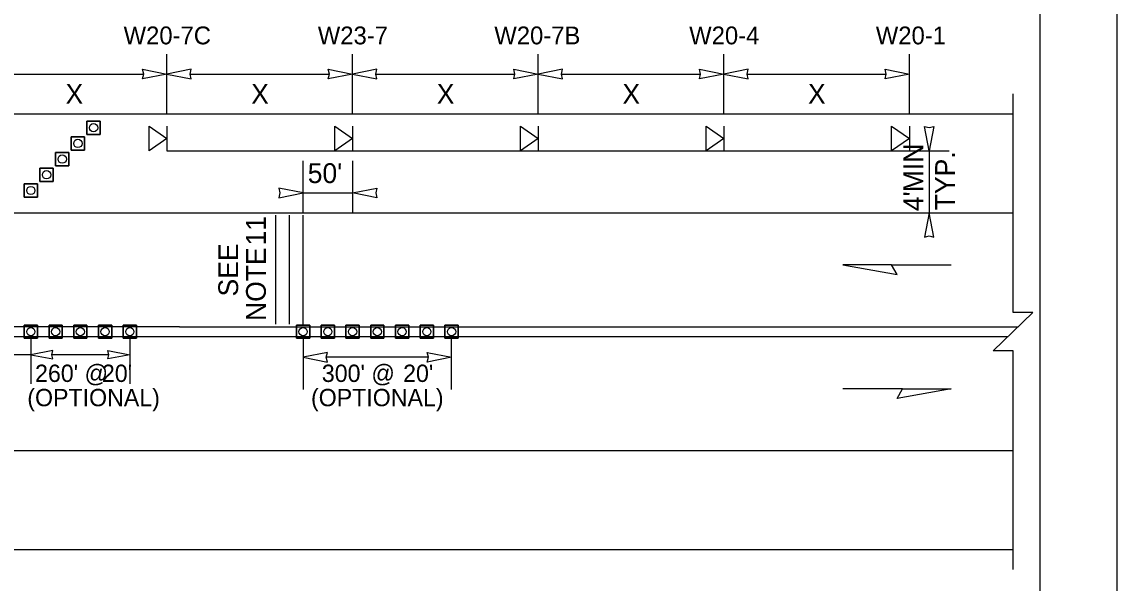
# Model space of a CAD drawing. Extents: x 99999.1 to 100095.7, y 99995 to 100010.7.
# Drawn here: x 100011.637 to 100016.062, y 100005.597 to 100007.863 of the extents above; entities that cross this region are included whole.
import ezdxf

# ---------------------------------------------------------------- set-up
doc = ezdxf.new("R2010")
doc.units = 0
for name, color, linetype in [('RD_ED_ShoulderPavedEdge', 7, 'Continuous'), ('RD_MK_LineDblYellowCenter', 7, 'Continuous'), ('RD_MK_LineEdgeWhite', 7, 'Continuous'), ('RD_MK_LineNoPass', 7, 'Continuous'), ('RD_MK_LineSkipCenter', 7, 'Continuous'), ('SH_GI_PlotLimits', 7, 'Continuous'), ('SH_GI_SheetBorder', 7, 'Continuous'), ('TR_SN_ConstructionSigns', 7, 'Continuous'), ('TR_WZ_PortableSignMountBlk-Org', 7, 'Continuous'), ('TR_WZ_TrafficCone', 7, 'Continuous'), ('TR_WZ_WorkZoneDetails', 7, 'Continuous'), ('TR_WZ_WorkZoneTextCurrent', 7, 'Continuous')]:
    doc.layers.add(name, color=color, linetype=linetype)

msp = doc.modelspace()

# ---------------------------------------------------------------- linework, layer by layer
at = {"layer": 'RD_ED_ShoulderPavedEdge'}
for p, q in [((100000.1076, 100007.4923), (100015.6424, 100007.4923)), ((100000.1076, 100005.7323), (100015.6424, 100005.7323))]:
    msp.add_line(p, q, dxfattribs=at)
at = {"layer": 'RD_MK_LineDblYellowCenter'}
for p, q in [((100012.2733, 100006.6323), (100015.6631, 100006.6323)), ((100012.2733, 100006.5923), (100015.6218, 100006.5923))]:
    msp.add_line(p, q, dxfattribs=at)
at = {"layer": 'RD_MK_LineEdgeWhite'}
for p, q in [((100000.1076, 100007.0923), (100015.6424, 100007.0923)), ((100000.1076, 100006.1323), (100015.6424, 100006.1323))]:
    msp.add_line(p, q, dxfattribs=at)
at = {"layer": 'RD_MK_LineNoPass'}
msp.add_line((100011.4733, 100006.5923), (100012.2733, 100006.5923), dxfattribs=at)
at = {"layer": 'RD_MK_LineSkipCenter'}
msp.add_lwpolyline([(100012.2733, 100006.6323), (100011.4733, 100006.6323)], dxfattribs=at)
at = {"layer": 'SH_GI_PlotLimits'}
msp.add_lwpolyline([(99999.0625, 99999.6875), (100016.0625, 99999.6875), (100016.0625, 100010.6875), (99999.0625, 100010.6875)], close=True, dxfattribs=at)
at = {"layer": 'SH_GI_SheetBorder'}
msp.add_line((100015.75, 100010.375), (100015.75, 100000), dxfattribs=at)
at = {"layer": 'TR_WZ_PortableSignMountBlk-Org'}
for p, q in [((100012.2233, 100007.4422), (100012.2233, 100007.3422)), ((100012.9733, 100007.4422), (100012.9733, 100007.3422)), ((100013.7233, 100007.4422), (100013.7233, 100007.3422)), ((100014.4733, 100007.4422), (100014.4733, 100007.3422)), ((100015.2233, 100007.4422), (100015.2233, 100007.3422))]:
    msp.add_line(p, q, dxfattribs=at)
for points in [[(100012.2233, 100007.3923), (100012.1515, 100007.3422), (100012.1515, 100007.4422)], [(100012.9733, 100007.3923), (100012.9015, 100007.3422), (100012.9015, 100007.4422)], [(100013.7233, 100007.3923), (100013.6515, 100007.3422), (100013.6515, 100007.4422)], [(100014.4733, 100007.3923), (100014.4015, 100007.3422), (100014.4015, 100007.4422)], [(100015.2233, 100007.3923), (100015.1515, 100007.3422), (100015.1515, 100007.4422)]]:
    msp.add_lwpolyline(points, close=True, dxfattribs=at)
at = {"layer": 'TR_WZ_TrafficCone'}
for points in [[(100011.9533, 100007.4623), (100011.9, 100007.4623), (100011.9, 100007.409), (100011.9533, 100007.409), (100011.9533, 100007.4623)], [(100011.9533, 100007.409), (100011.9, 100007.409), (100011.9, 100007.4623), (100011.9533, 100007.4623), (100011.9533, 100007.409)], [(100011.89, 100007.399), (100011.8367, 100007.399), (100011.8367, 100007.3457), (100011.89, 100007.3457), (100011.89, 100007.399)], [(100011.89, 100007.3457), (100011.8367, 100007.3457), (100011.8367, 100007.399), (100011.89, 100007.399), (100011.89, 100007.3457)], [(100011.8267, 100007.3357), (100011.7733, 100007.3357), (100011.7733, 100007.2823), (100011.8267, 100007.2823), (100011.8267, 100007.3357)], [(100011.8267, 100007.2823), (100011.7733, 100007.2823), (100011.7733, 100007.3357), (100011.8267, 100007.3357), (100011.8267, 100007.2823)], [(100011.7633, 100007.219), (100011.71, 100007.219), (100011.71, 100007.2723), (100011.7633, 100007.2723), (100011.7633, 100007.219)], [(100011.7633, 100007.2723), (100011.71, 100007.2723), (100011.71, 100007.219), (100011.7633, 100007.219), (100011.7633, 100007.2723)], [(100011.7, 100007.1557), (100011.6467, 100007.1557), (100011.6467, 100007.209), (100011.7, 100007.209), (100011.7, 100007.1557)], [(100011.7, 100007.209), (100011.6467, 100007.209), (100011.6467, 100007.1557), (100011.7, 100007.1557), (100011.7, 100007.209)], [(100011.7, 100006.639), (100011.6467, 100006.639), (100011.6467, 100006.5857), (100011.7, 100006.5857), (100011.7, 100006.639)], [(100011.7, 100006.5857), (100011.6467, 100006.5857), (100011.6467, 100006.639), (100011.7, 100006.639), (100011.7, 100006.5857)], [(100011.8, 100006.639), (100011.7467, 100006.639), (100011.7467, 100006.5857), (100011.8, 100006.5857), (100011.8, 100006.639)], [(100011.8, 100006.5857), (100011.7467, 100006.5857), (100011.7467, 100006.639), (100011.8, 100006.639), (100011.8, 100006.5857)], [(100011.9, 100006.639), (100011.8467, 100006.639), (100011.8467, 100006.5857), (100011.9, 100006.5857), (100011.9, 100006.639)], [(100011.9, 100006.5857), (100011.8467, 100006.5857), (100011.8467, 100006.639), (100011.9, 100006.639), (100011.9, 100006.5857)], [(100012, 100006.639), (100011.9467, 100006.639), (100011.9467, 100006.5857), (100012, 100006.5857), (100012, 100006.639)], [(100012, 100006.5857), (100011.9467, 100006.5857), (100011.9467, 100006.639), (100012, 100006.639), (100012, 100006.5857)], [(100012.1, 100006.639), (100012.0467, 100006.639), (100012.0467, 100006.5857), (100012.1, 100006.5857), (100012.1, 100006.639)], [(100012.1, 100006.5857), (100012.0467, 100006.5857), (100012.0467, 100006.639), (100012.1, 100006.639), (100012.1, 100006.5857)], [(100012.8, 100006.5857), (100012.7467, 100006.5857), (100012.7467, 100006.639), (100012.8, 100006.639), (100012.8, 100006.5857)], [(100012.8, 100006.639), (100012.7467, 100006.639), (100012.7467, 100006.5857), (100012.8, 100006.5857), (100012.8, 100006.639)], [(100012.9, 100006.5857), (100012.8467, 100006.5857), (100012.8467, 100006.639), (100012.9, 100006.639), (100012.9, 100006.5857)], [(100012.9, 100006.639), (100012.8467, 100006.639), (100012.8467, 100006.5857), (100012.9, 100006.5857), (100012.9, 100006.639)], [(100013, 100006.5857), (100012.9467, 100006.5857), (100012.9467, 100006.639), (100013, 100006.639), (100013, 100006.5857)], [(100013, 100006.639), (100012.9467, 100006.639), (100012.9467, 100006.5857), (100013, 100006.5857), (100013, 100006.639)], [(100013.1, 100006.5857), (100013.0467, 100006.5857), (100013.0467, 100006.639), (100013.1, 100006.639), (100013.1, 100006.5857)], [(100013.1, 100006.639), (100013.0467, 100006.639), (100013.0467, 100006.5857), (100013.1, 100006.5857), (100013.1, 100006.639)], [(100013.2, 100006.5857), (100013.1467, 100006.5857), (100013.1467, 100006.639), (100013.2, 100006.639), (100013.2, 100006.5857)], [(100013.2, 100006.639), (100013.1467, 100006.639), (100013.1467, 100006.5857), (100013.2, 100006.5857), (100013.2, 100006.639)], [(100013.3, 100006.5857), (100013.2467, 100006.5857), (100013.2467, 100006.639), (100013.3, 100006.639), (100013.3, 100006.5857)], [(100013.3, 100006.639), (100013.2467, 100006.639), (100013.2467, 100006.5857), (100013.3, 100006.5857), (100013.3, 100006.639)], [(100013.4, 100006.5857), (100013.3467, 100006.5857), (100013.3467, 100006.639), (100013.4, 100006.639), (100013.4, 100006.5857)], [(100013.4, 100006.639), (100013.3467, 100006.639), (100013.3467, 100006.5857), (100013.4, 100006.5857), (100013.4, 100006.639)]]:
    msp.add_lwpolyline(points, dxfattribs=at)
for centre in [(100011.9267, 100007.4357), (100011.8633, 100007.3723), (100011.8, 100007.309), (100011.7367, 100007.2457), (100011.6733, 100007.1823), (100011.6733, 100006.6123), (100011.7733, 100006.6123), (100011.8733, 100006.6123), (100011.9733, 100006.6123), (100012.0733, 100006.6123), (100012.7733, 100006.6123), (100012.8733, 100006.6123), (100012.9733, 100006.6123), (100013.0733, 100006.6123), (100013.1733, 100006.6123), (100013.2733, 100006.6123), (100013.3733, 100006.6123)]:
    msp.add_circle(centre, 0.0167, dxfattribs=at)
at = {"layer": 'TR_WZ_WorkZoneDetails'}
for p, q in [((100012.2233, 100007.4923), (100012.2233, 100007.7323)), ((100012.9733, 100007.4923), (100012.9733, 100007.7323)), ((100013.7233, 100007.4923), (100013.7233, 100007.7323)), ((100014.4733, 100007.4923), (100014.4733, 100007.7323)), ((100015.2233, 100007.4921), (100015.2233, 100007.7323)), ((100011.5671, 100007.6523), (100012.1296, 100007.6523)), ((100012.3171, 100007.6523), (100012.8796, 100007.6523)), ((100013.0671, 100007.6523), (100013.6296, 100007.6523)), ((100013.8171, 100007.6523), (100014.3796, 100007.6523)), ((100014.5671, 100007.6523), (100015.1296, 100007.6523)), ((100012.2233, 100007.3422), (100015.2233, 100007.3422)), ((100015.2233, 100007.3422), (100015.3833, 100007.3422)), ((100015.3033, 100007.3422), (100015.3033, 100007.0923)), ((100012.7733, 100007.0923), (100012.7733, 100007.3023)), ((100012.9733, 100007.3023), (100012.9733, 100007.0923)), ((100012.7733, 100007.1723), (100012.9733, 100007.1723)), ((100012.6628, 100006.6423), (100012.6628, 100007.0823)), ((100012.7185, 100006.6423), (100012.7185, 100007.0823)), ((100012.7733, 100006.6423), (100012.7733, 100007.0823)), ((100015.2233, 100007.0923), (100015.3833, 100007.0923)), ((100015.1513, 100006.8816), (100015.3924, 100006.8816)), ((100011.6733, 100006.5857), (100011.6733, 100006.4023)), ((100012.0733, 100006.5857), (100012.0733, 100006.4023)), ((100012.7733, 100006.589), (100012.7733, 100006.379)), ((100013.3733, 100006.379), (100013.3733, 100006.589)), ((100011.6733, 100006.5193), (100011.4733, 100006.5193)), ((100011.989, 100006.5193), (100011.7577, 100006.5193)), ((100013.2796, 100006.509), (100012.8671, 100006.509)), ((100015.1959, 100006.3816), (100014.9548, 100006.3816))]:
    msp.add_line(p, q, dxfattribs=at)
for points in [[(100012.2233, 100007.6523), (100012.1251, 100007.6331), (100012.1296, 100007.6523), (100012.1251, 100007.6716)], [(100012.2233, 100007.6523), (100012.3216, 100007.6331), (100012.3171, 100007.6523), (100012.3216, 100007.6716)], [(100012.9733, 100007.6523), (100012.8751, 100007.6331), (100012.8796, 100007.6523), (100012.8751, 100007.6716)], [(100012.9733, 100007.6523), (100013.0716, 100007.6331), (100013.0671, 100007.6523), (100013.0716, 100007.6716)], [(100013.7233, 100007.6523), (100013.6251, 100007.6331), (100013.6296, 100007.6523), (100013.6251, 100007.6716)], [(100013.7233, 100007.6523), (100013.8216, 100007.6331), (100013.8171, 100007.6523), (100013.8216, 100007.6716)], [(100014.4733, 100007.6523), (100014.3751, 100007.6331), (100014.3796, 100007.6523), (100014.3751, 100007.6716)], [(100014.4733, 100007.6523), (100014.5716, 100007.6331), (100014.5671, 100007.6523), (100014.5716, 100007.6716)], [(100015.2233, 100007.6523), (100015.1251, 100007.6331), (100015.1296, 100007.6523), (100015.1251, 100007.6716)], [(100015.3033, 100007.3422), (100015.2841, 100007.4405), (100015.3033, 100007.436), (100015.3226, 100007.4405)], [(100012.7733, 100007.1723), (100012.6751, 100007.1916), (100012.6796, 100007.1723), (100012.6751, 100007.1531)], [(100012.9733, 100007.1723), (100013.0716, 100007.1916), (100013.0671, 100007.1723), (100013.0716, 100007.1531)], [(100015.3033, 100007.0923), (100015.2841, 100006.9941), (100015.3033, 100006.9986), (100015.3226, 100006.9941)], [(100014.9548, 100006.8816), (100015.1736, 100006.843), (100015.1513, 100006.8816)], [(100011.6733, 100006.5193), (100011.7618, 100006.502), (100011.7577, 100006.5193), (100011.7618, 100006.5367)], [(100012.0733, 100006.5193), (100011.9849, 100006.502), (100011.989, 100006.5193), (100011.9849, 100006.5367)], [(100012.7733, 100006.509), (100012.8716, 100006.4897), (100012.8671, 100006.509), (100012.8716, 100006.5283)], [(100013.3733, 100006.509), (100013.2751, 100006.4897), (100013.2796, 100006.509), (100013.2751, 100006.5283)], [(100015.3924, 100006.3816), (100015.1736, 100006.343), (100015.1959, 100006.3816)]]:
    msp.add_lwpolyline(points, close=True, dxfattribs=at)
msp.add_lwpolyline([(100015.6424, 100005.6523), (100015.6424, 100006.5349), (100015.5624, 100006.5349), (100015.7225, 100006.6898), (100015.6424, 100006.6898), (100015.6424, 100007.5723)], dxfattribs=at)

# ---------------------------------------------------------------- texts
at = {"layer": 'TR_SN_ConstructionSigns'}
for s, p in [('W20-7C', (100012.0481, 100007.7723)), ('W23-7', (100012.8328, 100007.7723)), ('W20-7B', (100013.546, 100007.7723)), ('W20-4', (100014.3334, 100007.7723)), ('W20-1', (100015.0875, 100007.7723))]:
    msp.add_text(s, height=0.072, rotation=360, dxfattribs=at).set_placement(p)
at = {"layer": 'TR_WZ_WorkZoneDetails'}
for s, p in [('11', (100012.6228, 100006.9604)), ('SEE', (100012.5108, 100006.7544)), ('NOTE', (100012.6228, 100006.6555))]:
    msp.add_text(s, height=0.08, rotation=90, dxfattribs=at).set_placement(p)
at = {"layer": 'TR_WZ_WorkZoneTextCurrent'}
for s, height, p in [('X', 0.08, (100011.8136, 100007.5323)), ('X', 0.08, (100012.5636, 100007.5323)), ('X', 0.08, (100013.3136, 100007.5323)), ('X', 0.08, (100014.0636, 100007.5323)), ('X', 0.08, (100014.8136, 100007.5323)), ("50'", 0.08, (100012.7921, 100007.2123)), ("260' @", 0.07, (100011.6903, 100006.4093)), ("300' @", 0.07, (100012.8491, 100006.4093)), ("20'", 0.07, (100011.9604, 100006.4093)), ("20'", 0.07, (100013.1775, 100006.4093)), ('(OPTIONAL)', 0.07, (100011.659, 100006.3113)), ('(OPTIONAL)', 0.07, (100012.8053, 100006.3113))]:
    msp.add_text(s, height=height, dxfattribs=at).set_placement(p)
for s, p in [('MIN', (100015.2793, 100007.1754)), ('TYP.', (100015.4073, 100007.1026)), ("4'", (100015.2793, 100007.0989))]:
    msp.add_text(s, height=0.08, rotation=90, dxfattribs=at).set_placement(p)

doc.saveas('drawing.dxf')
